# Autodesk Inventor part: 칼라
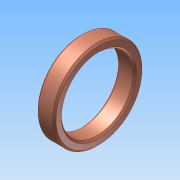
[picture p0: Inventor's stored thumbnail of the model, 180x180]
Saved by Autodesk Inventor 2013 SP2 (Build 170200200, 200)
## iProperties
Created: 2025-09
Part Number: 칼라
Material: Generic
Document SubType Name: Modeling
Designer: a
Density: 1 g/cm^3
Author: a
변환 표준: STEP AP214IS
전처리기: Build: 200, Release: 2013 SP2 Update 6 - Date: Thu 07/17/2014
전송 단위: 밀리미터
불확실성: 0.01
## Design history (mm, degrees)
node "칼라1"
node "솔리드1"
node "기준1"
